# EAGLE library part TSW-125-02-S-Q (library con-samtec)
THROUGH-HOLE .025" SQ POST HEADER Source: Samtec TSW.pdf
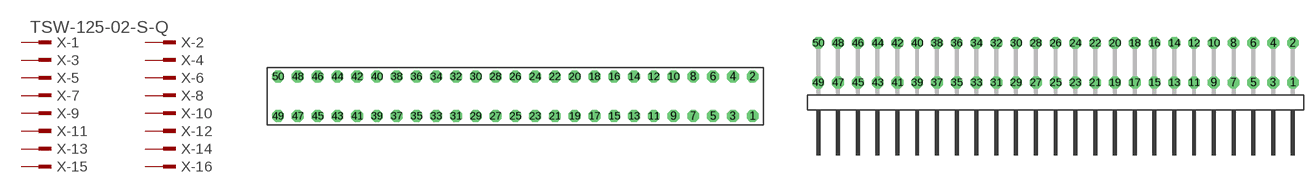
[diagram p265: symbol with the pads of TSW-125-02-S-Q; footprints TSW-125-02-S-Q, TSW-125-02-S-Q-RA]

Designator prefix X; gates -1=MPINV -2=MPIN -3=MPIN -4=MPIN -5=MPIN -6=MPIN -7=MPIN -8=MPIN -9=MPIN -10=MPIN -11=MPIN -12=MPIN -13=MPIN -14=MPIN -15=MPIN -16=MPIN -17=MPIN -18=MPIN -19=MPIN -20=MPIN -21=MPIN -22=MPIN -23=MPIN -24=MPIN -25=MPIN -26=MPIN -27=MPIN -28=MPIN -29=MPIN -30=MPIN -31=MPIN -32=MPIN -33=MPIN -34=MPIN -35=MPIN -36=MPIN -37=MPIN -38=MPIN -39=MPIN -40=MPIN -41=MPIN -42=MPIN -43=MPIN -44=MPIN -45=MPIN -46=MPIN -47=MPIN -48=MPIN -49=MPIN -50=MPIN

## TSW-125-02-S-Q (OC_FARNELL: unknown; OC_NEWARK: unknown)  [TSW-125-02-S-Q]
1  -1:1  pas
2  -2:1  pas
3  -3:1  pas
4  -4:1  pas
5  -5:1  pas
6  -6:1  pas
7  -7:1  pas
8  -8:1  pas
9  -9:1  pas
10  -10:1  pas
11  -11:1  pas
12  -12:1  pas
13  -13:1  pas
14  -14:1  pas
15  -15:1  pas
16  -16:1  pas
17  -17:1  pas
18  -18:1  pas
19  -19:1  pas
20  -20:1  pas
21  -21:1  pas
22  -22:1  pas
23  -23:1  pas
24  -24:1  pas
25  -25:1  pas
26  -26:1  pas
27  -27:1  pas
28  -28:1  pas
29  -29:1  pas
30  -30:1  pas
31  -31:1  pas
32  -32:1  pas
33  -33:1  pas
34  -34:1  pas
35  -35:1  pas
36  -36:1  pas
37  -37:1  pas
38  -38:1  pas
39  -39:1  pas
40  -40:1  pas
41  -41:1  pas
42  -42:1  pas
43  -43:1  pas
44  -44:1  pas
45  -45:1  pas
46  -46:1  pas
47  -47:1  pas
48  -48:1  pas
49  -49:1  pas
50  -50:1  pas

## TSW-125-02-S-Q-RA (OC_FARNELL: unknown; OC_NEWARK: unknown)  [TSW-125-02-S-Q-RA]
Pads as for TSW-125-02-S-Q

## Footprint TSW-125-02-S-Q (pad centres in mm)
THROUGH-HOLE .025" SQ POST HEADER Source: Samtec TSW.pdf
drill 1 pad 1.5 octagon: 1 30.48,-2.54; 2 30.48,2.54; 3 27.94,-2.54; 4 27.94,2.54; 5 25.4,-2.54; 6 25.4,2.54; 7 22.86,-2.54; 8 22.86,2.54; 9 20.32,-2.54; 10 20.32,2.54; 11 17.78,-2.54; 12 17.78,2.54; 13 15.24,-2.54; 14 15.24,2.54; 15 12.7,-2.54; 16 12.7,2.54; 17 10.16,-2.54; 18 10.16,2.54; 19 7.62,-2.54; 20 7.62,2.54; 21 5.08,-2.54; 22 5.08,2.54; 23 2.54,-2.54; 24 2.54,2.54; 25 0,-2.54; 26 0,2.54; 27 -2.54,-2.54; 28 -2.54,2.54; 29 -5.08,-2.54; 30 -5.08,2.54; 31 -7.62,-2.54; 32 -7.62,2.54; 33 -10.16,-2.54; 34 -10.16,2.54; 35 -12.7,-2.54; 36 -12.7,2.54; 37 -15.24,-2.54; 38 -15.24,2.54; 39 -17.78,-2.54; 40 -17.78,2.54; 41 -20.32,-2.54; 42 -20.32,2.54; 43 -22.86,-2.54; 44 -22.86,2.54; 45 -25.4,-2.54; 46 -25.4,2.54; 47 -27.94,-2.54; 48 -27.94,2.54; 49 -30.48,-2.54; 50 -30.48,2.54

## Footprint TSW-125-02-S-Q-RA (pad centres in mm)
THROUGH-HOLE .025" SQ POST HEADER Source: Samtec TSW.pdf
drill 1 pad 1.5 octagon: 1 30.48,1.524; 2 30.48,6.604; 3 27.94,1.524; 4 27.94,6.604; 5 25.4,1.524; 6 25.4,6.604; 7 22.86,1.524; 8 22.86,6.604; 9 20.32,1.524; 10 20.32,6.604; 11 17.78,1.524; 12 17.78,6.604; 13 15.24,1.524; 14 15.24,6.604; 15 12.7,1.524; 16 12.7,6.604; 17 10.16,1.524; 18 10.16,6.604; 19 7.62,1.524; 20 7.62,6.604; 21 5.08,1.524; 22 5.08,6.604; 23 2.54,1.524; 24 2.54,6.604; 25 0,1.524; 26 0,6.604; 27 -2.54,1.524; 28 -2.54,6.604; 29 -5.08,1.524; 30 -5.08,6.604; 31 -7.62,1.524; 32 -7.62,6.604; 33 -10.16,1.524; 34 -10.16,6.604; 35 -12.7,1.524; 36 -12.7,6.604; 37 -15.24,1.524; 38 -15.24,6.604; 39 -17.78,1.524; 40 -17.78,6.604; 41 -20.32,1.524; 42 -20.32,6.604; 43 -22.86,1.524; 44 -22.86,6.604; 45 -25.4,1.524; 46 -25.4,6.604; 47 -27.94,1.524; 48 -27.94,6.604; 49 -30.48,1.524; 50 -30.48,6.604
